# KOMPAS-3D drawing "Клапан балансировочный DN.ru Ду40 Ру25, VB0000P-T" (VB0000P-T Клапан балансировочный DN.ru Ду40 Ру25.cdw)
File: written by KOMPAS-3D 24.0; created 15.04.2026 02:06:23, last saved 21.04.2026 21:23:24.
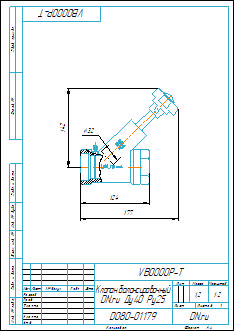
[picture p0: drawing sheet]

Document properties: Автор: DN.ru; Форматы листов документа: A4; Полное имя файла: VB0000P-T Клапан балансировочный DN.ru Ду40 Ру25.m3d; Масса: 1.2; Наименование: Клапан балансировочный DN.ru Ду40 Ру25; Количество листов документа: 1; Примечание: D080-01179

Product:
- Part/product: Клапан балансировочный DN.ru Ду40 Ру25  | designation VB0000P-T
    Масса: 1.2
    Раздел спецификации: Прочие изделия
    Примечание: D080-01179

Views: Вид 1, Местный разрез 1, Вид:1
Referenced files in C:\Работа\VB0000P-T DN X PN 25 Клапан балансировочный DN.ru\DN15\: VB0000P-T DN15 PN25 Клапан балансировочный DN.ru.m3d
Referenced files in E:\Работа\Зайцев\АУТСОРС\Диман\Балансировка\VB0000P-T Клапан балансировочный DN.ru Ду15-50 Ру25\DN40\: VB0000P-T Клапан балансировочный DN.ru Ду40 Ру25.m3d
Referenced files in C:\Program Files\ASCON\KOMPAS-3D v24\Templates\: Чертеж_DN.ru.cdt
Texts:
  VB0000P-T
  Чертеж_DN.ru.cdt
  Клапан балансировочный
  DN.ru Ду40 Ру25
  Клапан балансировочный DN.ru Ду40 Ру25
  VB0000P-T Клапан балансировочный DN.ru Ду40 Ру25
Dimensions and other numbers on the sheet: 0; 3; 2; 4; 124; 142; 177; 1:2; 1; 1,2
